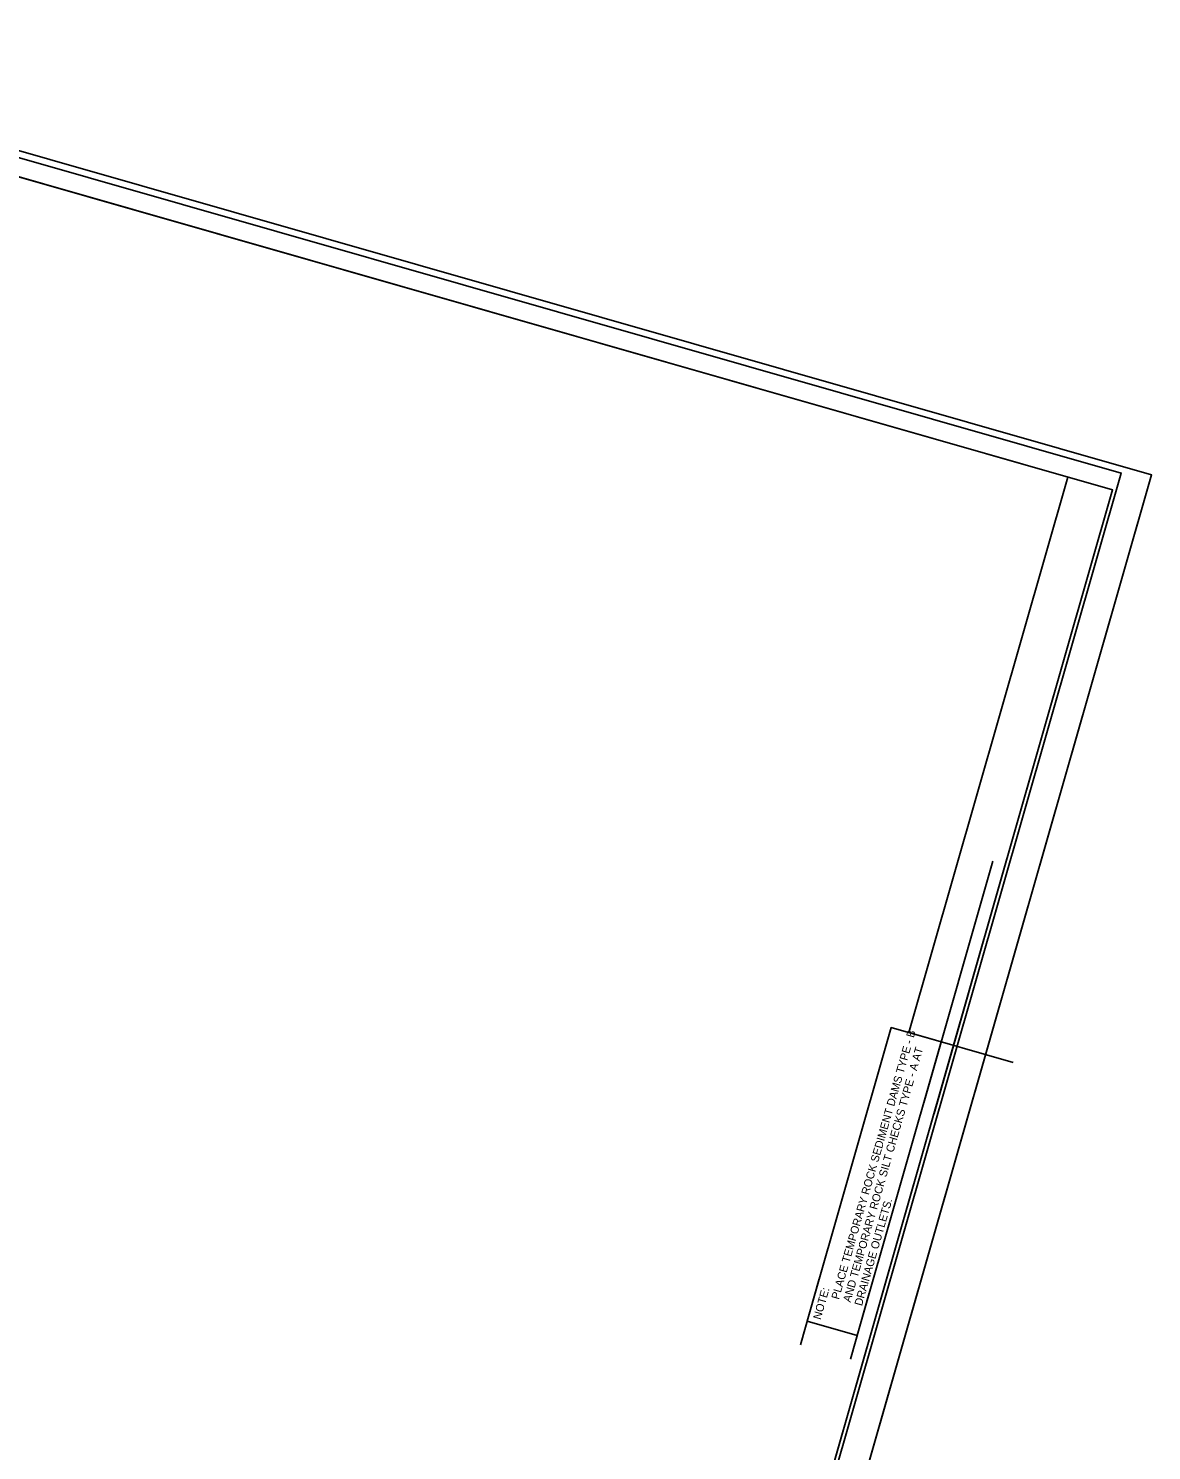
# Model space of a CAD drawing. Extents: x 2096976 to 2098492, y 681809 to 689636.
# Drawn here: x 2097734 to 2098492, y 688676 to 689636 of the extents above; entities that cross this region are included whole.
import ezdxf

# ---------------------------------------------------------------- set-up
doc = ezdxf.new("R2010")
doc.units = 0
for name, color, linetype in [('Construction Sheet Number Note CG CELL', 7, 'Continuous'), ('Scratch_Level_0', 7, 'Continuous'), ('Sheet Block Title CELL', 7, 'Continuous'), ('Sheet Data Field CELL', 7, 'Continuous'), ('Sheet Plan And Profile CELL', 7, 'Continuous'), ('Sheet Plot Border Inside CELL', 7, 'Continuous'), ('Sheet Sticker Exception Certification CELL', 7, 'Continuous')]:
    doc.layers.add(name, color=color, linetype=linetype)

msp = doc.modelspace()

# ---------------------------------------------------------------- linework, layer by layer
at = {"layer": 'Construction Sheet Number Note CG CELL'}
msp.add_lwpolyline([(2098259.31, 688763.3), (2098316.02, 688961.41), (2098349.76, 688951.76), (2098293.07, 688753.64)], close=True, dxfattribs=at)
at = {"layer": 'Scratch_Level_0'}
for p, q in [((2098435.32, 689332.93), (2098327.99, 688957.99)), ((2098337.99, 688910.64), (2098384.68, 689073.75)), ((2098344.95, 688903.45), (2098391.64, 689066.57)), ((2098327.99, 688957.99), (2098398.38, 688937.84)), ((2098267.48, 688791.82), (2098254.74, 688747.32)), ((2098301.23, 688782.16), (2098288.49, 688737.66)), ((2098259.3, 688763.3), (2098293.07, 688753.64))]:
    msp.add_line(p, q, dxfattribs=at)
at = {"layer": 'Sheet Block Title CELL'}
msp.add_lwpolyline([(2098028.44, 687715.97), (2098491.74, 689334.46), (2097439.02, 689635.81), (2096975.72, 688017.32)], close=True, dxfattribs=at)
at = {"layer": 'Sheet Data Field CELL'}
msp.add_lwpolyline([(2098012.79, 687733.97), (2098471.26, 689335.63), (2097457.01, 689625.98), (2096998.53, 688024.31)], close=True, dxfattribs=at)
at = {"layer": 'Sheet Plan And Profile CELL'}
msp.add_line((2098028.44, 687715.97), (2098491.74, 689334.46), dxfattribs=at)
at = {"layer": 'Sheet Plot Border Inside CELL'}
for points in [[(2098102.1, 688055.1), (2097347.73, 688084.03), (2097043.16, 688171.19), (2097346.07, 689229.4), (2097355.46, 689262.19), (2097400.9, 689420.95), (2097628.1, 689355.93), (2097683.15, 689548.26), (2098465.42, 689324.31)], [(2098102.1, 688055.1), (2097347.73, 688084.03), (2097043.16, 688171.19), (2097345.95, 689228.93), (2097355.46, 689262.19), (2097400.91, 689420.95), (2097628.1, 689355.93), (2097683.15, 689548.26), (2098465.42, 689324.31)]]:
    msp.add_lwpolyline(points, close=True, dxfattribs=at)
at = {"layer": 'Sheet Sticker Exception Certification CELL'}
for points in [[(2097455.97, 689613.3), (2097043.16, 688171.19), (2098052.61, 687882.22), (2098465.42, 689324.31)], [(2098052.61, 687882.22), (2097043.17, 688171.15), (2097400.9, 689420.95), (2097545.17, 689379.67), (2097600.23, 689571.98), (2098465.42, 689324.31)]]:
    msp.add_lwpolyline(points, close=True, dxfattribs=at)

# ---------------------------------------------------------------- texts
at = {"layer": 'Construction Sheet Number Note CG CELL'}
for s, p in [('PLACE TEMPORARY ROCK SEDIMENT DAMS TYPE - B', (2098280.68, 688777.5)), ('AND TEMPORARY ROCK SILT CHECKS TYPE - A AT', (2098288.53, 688775.64)), ('DRAINAGE OUTLETS.', (2098296.25, 688773.16)), ('NOTE:', (2098268.36, 688763.88))]:
    msp.add_text(s, height=5.4, rotation=74.03119, dxfattribs=at).set_placement(p)

doc.saveas('drawing.dxf')
